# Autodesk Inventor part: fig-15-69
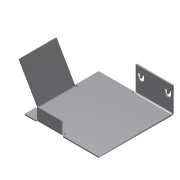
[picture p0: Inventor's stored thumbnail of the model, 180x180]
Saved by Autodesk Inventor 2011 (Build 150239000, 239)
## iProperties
Shininess: 77.0
Angle Display Precision: 2
Document Length Units: 11269
Document Angle Units: 11279
Document Time Units: 11290
Document Mass Units: 11283
Document Length Units Precision: 3
Document Angle Units Precision: 2
Created: 2002-04
Part Number: fig-15-69
Document SubType Name: Sheet Metal
Density: 1 g/cm^3
Sheet Metal Rule: Default
Density: 0.0
Volumn: 0.0
Area: 0.0
PropertySet Name: Model Information
Control State: 0
Master: False
Checked Out: False
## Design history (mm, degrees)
node "Face1"
  sketch "Sketch1"
    geometry: L1 (12.647, 25.882)-(12.647, -14.118); L2 (12.647, -14.118)-(-17.353, -14.118); L3 (-17.353, -14.118)-(-17.353, 15.882); L4 (-17.353, 15.882)-(-2.353, 15.882); L5 (-2.353, 15.882)-(-2.353, 25.882); L6 (-2.353, 25.882)-(12.647, 25.882); 1 further point
    constraints: 12 end point, 4 parallel, 1 perpendicular
    dimensions: "d5" = 30 distance of L2.end L3.end; "d6" = 10 distance of L4.end L5.end; "d7" = 15 distance of L3.end L4.end; "d25" = 15 distance of L5.end L1.start
sketch "Sketch3"
  geometry: L1 (10, -15)-(10, 0)
  constraints: 2 end point
feature "Fold3" sketch "Sketch3" dims "d26" = 0.5 (= BendRadius), "d27" = 90 deg, "d28" = 0.5 (= BendRadius), "d96" = 0.5 (= BendReliefWidth), "d97" = 0.25 (= BendReliefDepth), "d98" = 1 (= MinimumRemnant), "SeamGap" = 0.01, "Thickness" = 0.5
node "Flange2"
sketch "Sketch6"
  geometry: L1 (-6.914, 3.413)-(-5.843, 3.413); L2 (-5.843, 0.624)-(-6.914, 0.624); L3 (-6.914, 2.432)-(-5.843, 2.432); L4 (-5.843, 1.605)-(-6.914, 1.605); L5 (-6.914, 0.624)-(-6.914, 1.605); L6 (-6.914, 2.432)-(-6.914, 3.413); L7 (-6.914, 12.568)-(-6.914, 11.587); L8 (-6.914, 14.376)-(-6.914, 13.395); L9 (-6.914, 11.587)-(-5.843, 11.587); L10 (-5.843, 14.376)-(-6.914, 14.376); L11 (-6.914, 12.568)-(-5.843, 12.568); L12 (-5.843, 13.395)-(-6.914, 13.395); A1 r 1.394 centre (-5.843, 2.018) between (-5.843, 0.624) and (-5.843, 3.413); A2 r 0.413 centre (-5.843, 2.018) between (-5.843, 1.605) and (-5.843, 2.432); A3 r 1.394 centre (-5.843, 12.982) between (-5.843, 11.587) and (-5.843, 14.376); A4 r 0.413 centre (-5.843, 12.982) between (-5.843, 12.568) and (-5.843, 13.395)
  constraints: 24 end point, 8 point on circle, 4 centre point, 3 equal length, 1 perpendicular
cut "Cut1" sketch "Sketch6" dims "d49" = 0.5 (= Thickness), "d50" = 0
node "Flange3"
body "Solid1"
face "Plate1" dims "Thickness" = 0.5
sketch "Sketch5"
  geometry: L1 (20, 0)-(5, 0); L2 (5, 0)-(5, 15); L3 (5, 15)-(20, 15); L4 (20, 15)-(20, 0)
  constraints: 8 end point
face "Plate6" dims "d35" = 10, "d36" = 5, "d38" = 15, "d39" = 60 deg, "d40" = 0.5 (= BendRadius), "Thickness" = 0.5, "MinimumRemnant" = 1 (= 2 x Thickness), "BendReliefWidth" = 0.5 (= Thickness)
bend "Bend5" dims "d38" = 15, "d39" = 60 deg, "d40" = 0.5 (= BendRadius), "d99" = 0.5 (= BendReliefWidth), "d100" = 0.25 (= BendReliefDepth), "d101" = 1 (= MinimumRemnant), "SeamGap" = 0.01, "Thickness" = 0.5, "MinimumRemnant" = 1 (= 2 x Thickness), "BendReliefWidth" = 0.5 (= Thickness), "TransitionRadius" = 0.5 (= BendRadius)
sketch "Sketch7"
  geometry: L1 (25, 0)-(15, 0); L2 (15, 0)-(15, 5); L3 (15, 5)-(25, 5); L4 (25, 5)-(25, 0)
  constraints: 8 end point
face "Plate7" dims "d57" = 5, "d58" = 10, "d60" = 5, "d61" = 90 deg, "d62" = 0.5 (= BendRadius), "Thickness" = 0.5, "MinimumRemnant" = 1 (= 2 x Thickness), "BendReliefWidth" = 0.5 (= Thickness)
bend "Bend7" dims "d59" = 0.5 (= BendRadius), "d60" = 5, "d61" = 90 deg, "d62" = 0.5 (= BendRadius), "d102" = 0.5 (= BendReliefWidth), "d103" = 0.25 (= BendReliefDepth), "d104" = 1 (= MinimumRemnant), "SeamGap" = 0.01, "Thickness" = 0.5, "MinimumRemnant" = 1 (= 2 x Thickness), "BendReliefWidth" = 0.5 (= Thickness)
other parameters: "BendRadius" = 0.5 (= Thickness), "BendReliefDepth" = 0.25 (= 0.5 x Thickness), "CornerReliefSize" = 2 (= 4 x Thickness), "d0" = 0.5 (= BendRadius), "d13" = 0.5 (= BendRadius), "d31" = 0.5 (= BendRadius), "d37" = 0.5 (= BendRadius), "JacobiRadiusSize" = 0.5 (= Thickness), "GapSize" = 0.5 (= Thickness)
